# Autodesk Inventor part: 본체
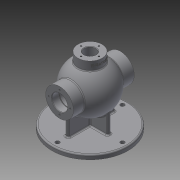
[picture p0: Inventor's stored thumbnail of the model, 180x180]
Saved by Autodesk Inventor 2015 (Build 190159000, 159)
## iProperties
Created: 2020-08
Part Number: 본체
Material: 일반
Document SubType Name: Modeling
Designer: 1019876
Density: 1 g/cm^3
Appearance: 기본값
Author: 1019876
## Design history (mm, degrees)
sketch "스케치1"
  geometry: C1 r 85 at (0, 0); 1 further point
  constraints: 1 centre point, 1 coincident
  dimensions: "d0" = 170 diameter of C1
extrude "돌출1" new body sketch "스케치1" distance "d1" = 10; taper "d2" = 0 deg
sketch "스케치2"
  geometry: L1 (43, 4)-(43, -4); L2 (-43, -4)-(-43, 4); L3 (-43, 4)-(43, -4); L4 (43, 4)-(-43, -4); L5 (-4, 52)-(4, 52); L6 (4, -52)-(-4, -52); L7 (-4, 52)-(4, -52); L8 (4, 52)-(-4, -52); L9 (4, 52)-(4, 4); L10 (4, -4)-(4, -52); L11 (-4, -52)-(-4, -4); L12 (-4, -0.372)-(-4, 0.372); L13 (-4, 4)-(-4, 52); L14 (4, 4)-(43, 4); L15 (-43, 4)-(-4, 4); L16 (43, -4)-(4, -4); L17 (-4, -4)-(-43, -4); C1 r 85 at (0, 0) reference
  constraints: 34 end point, 12 parallel, 4 midpoint, 4 perpendicular, 3 horizontal, 2 point on line
  dimensions: "d3" = 86 distance of L1.end L2.start; "d4" = 8 distance of L1.start L1.end; "d5" = 104 distance of L5.end L6.start; "d6" = 8 distance of L6.start L6.end
extrude "돌출2" join sketch "스케치2" distance "d7" = 75; taper "d8" = 0 deg
sketch "스케치3"
  geometry: L1 (85, 10)-(85, 0) reference; L2 (85, 0)-(-85, 0) reference; L3 (-85, 0)-(-85, 10) reference; L4 (-85, 10)-(-52, 10) reference; L5 (-52, 10)-(-52, 85) reference; L6 (-52, 85)-(52, 85) reference; L7 (52, 85)-(52, 10) reference; L8 (52, 10)-(85, 10) reference; L9 (68, 85)-(-68, 85); L10 (-68, 85)-(-68, 116); L11 (68, 85)-(68, 116); L12 (68, 116)-(42.988, 116); L13 (-42.988, 116)-(-68, 116); A1 r 53 centre (0, 85) between (42.988, 116) and (-42.988, 116); 1 further point
  constraints: 10 end point, 3 parallel, 2 point on circle, 1 centre point, 1 midpoint, 1 vertical
  dimensions: "d9" = 106 diameter of A1; "d12" = 136 distance of L9.start L9.end
revolve "회전1" sketch "스케치3" stored, may be unused: angle "d14" = 90 deg
node "작업 평면1"
sketch "스케치6"
  geometry: C1 r 27 at (0, 0); 1 further point
  constraints: 1 centre point, 1 coincident
  dimensions: "d29" = 54 diameter of C1
extrude "돌출3" join sketch "스케치6" distance "d30" = 54 (= d29); taper "d31" = 0 deg
sketch "스케치4"
  geometry: C1 r 31 at (0, 0) reference; 1 further point
hole "구멍1" sketch "스케치4" at (0, 0) diameter "d15" = 35; stored, may be unused: countersink angle "d19" = 90 deg, drill point angle "d21" = 118 deg; dims "d16" = 6, "d17" = 4, "d18" = 2, "d20" = 8
sketch "스케치5"
  geometry: L1 (42.988, 116)-(68, 116) reference; L2 (68, 116)-(68, 102.5) reference; L3 (68, 102.5)-(-68, 102.5) reference; L4 (-68, 102.5)-(-68, 116) reference; L5 (-68, 116)-(-42.988, 116) reference; L6 (85, 10)-(85, 0) reference; L7 (85, 0)-(-85, 0) reference; L8 (-85, 0)-(-85, 10) reference; L9 (-85, 10)-(-52, 10) reference; L10 (-52, 10)-(-52, 54) reference; L11 (-52, 54)-(-68, 54) reference; L12 (-68, 54)-(-68, 67.5) reference; L13 (-68, 67.5)-(68, 67.5) reference; L14 (68, 67.5)-(68, 54) reference; L15 (68, 54)-(52, 54) reference; L16 (52, 54)-(52, 10) reference; L17 (52, 10)-(85, 10) reference; L18 (-68, 67.5)-(-68, 102.5) reference; L19 (-68, 85)-(68, 85); L20 (-52, 85)-(-52, 103.5); L21 (-50.25, 85)-(-50.25, 103.5); L22 (-52, 103.5)-(-50.25, 103.5); L23 (-27, 130.607)-(-27, 150) reference; L24 (-27, 150)-(27, 150) reference; L25 (27, 150)-(27, 130.607) reference; A1 r 43 centre (0, 85) between (43, 85) and (-43, 85); A2 r 53 centre (0, 85) between (-27, 130.607) and (-42.988, 116) reference; A3 r 53 centre (0, 85) between (42.988, 116) and (27, 130.607) reference; 2 further points
  constraints: 8 end point, 5 point on line, 3 parallel, 2 point on circle, 1 centre point, 1 coincident, 1 horizontal, 1 midpoint
  dimensions: "d22" = 86 diameter of A1; "d23" = 16 distance between parallel lines of L18 L20; "d24" = 1.75 distance between parallel lines of L20 L21
revolve "회전2" sketch "스케치5" stored, may be unused: angle "d27" = 90 deg
sketch "스케치7"
  geometry: C1 r 27 at (0, 0) reference
hole "구멍2" sketch "스케치7" at (0, 0) diameter "d32" = 26; stored, may be unused: countersink angle "d36" = 90 deg, drill point angle "d38" = 118 deg; dims "d33" = 6, "d34" = 4, "d35" = 2, "d37" = 65
sketch "스케치8"
  geometry: C1 r 85 at (0, 0) reference; 1 further point
  constraints: 1 horizontal alignment
  dimensions: "d39" = 72.5 distance of C1.centre point (-72.5, 0)
hole "구멍3" sketch "스케치8" at (-72.5, 0) diameter "d40" = 9; stored, may be unused: countersink angle "d44" = 90 deg, drill point angle "d46" = 118 deg; dims "d41" = 6, "d42" = 4, "d43" = 2, "d45" = 65
sketch "스케치9"
  geometry: C1 r 17.5 at (0, 0) reference; 2 further points
  constraints: 1 vertical alignment
  dimensions: "d50" = 24 distance of point (0, 24) C1.centre
hole "구멍4" sketch "스케치9" at (0, 24) diameter "d51" = 3.242; stored, may be unused: countersink angle "d55" = 90 deg, drill point angle "d57" = 118 deg; dims "d52" = 12, "d53" = 4, "d54" = 2, "d56" = 15
sketch "스케치10"
  geometry: C1 r 13 at (0, 0) reference; 1 further point
  constraints: 1 horizontal alignment
  dimensions: "d61" = 20 distance of C1.centre point (-20, 0)
hole "구멍5" sketch "스케치10" at (-20, 0) diameter "d62" = 3.242; stored, may be unused: countersink angle "d66" = 90 deg, drill point angle "d68" = 118 deg; dims "d63" = 12, "d64" = 4, "d65" = 2, "d67" = 15
node "작업 평면2"
sketch "스케치11"
  geometry: L1 (-27, 0)-(27, 0) reference; 2 further points
  constraints: 1 other
  dimensions: "d73" = 27 horizontal distance of point (0, -9) L1.start; "d74" = 9 vertical distance of point (0, -9) L1.start
feature "엠보싱1" sketch "스케치11" dims "d1" = 10, "d2" = 0, "d75" = 0.5, "d76" = 0
chamfer "모따기1" distance "d77" = 1; stored, may be unused: second distance "d78" = 2, angle "d79" = 45 deg
fillet "모깎기1" dims "d80" = 3
fillet "모깎기2" dims "d81" = 3
fillet "모깎기3" dims "d82" = 3
fillet "모깎기4" dims "d83" = 3
node "솔리드1"
pattern_circular "원형 패턴1" dims angle "d48" = 360 deg
pattern_circular "원형 패턴2" dims angle "d59" = 360 deg
mirror "대칭1"
pattern_circular "원형 패턴3" dims angle "d70" = 360 deg
node "절단 모서리 투영1"
node "절단 모서리 투영2"
other parameters: "d13" = 31, "d25" = 18.5
